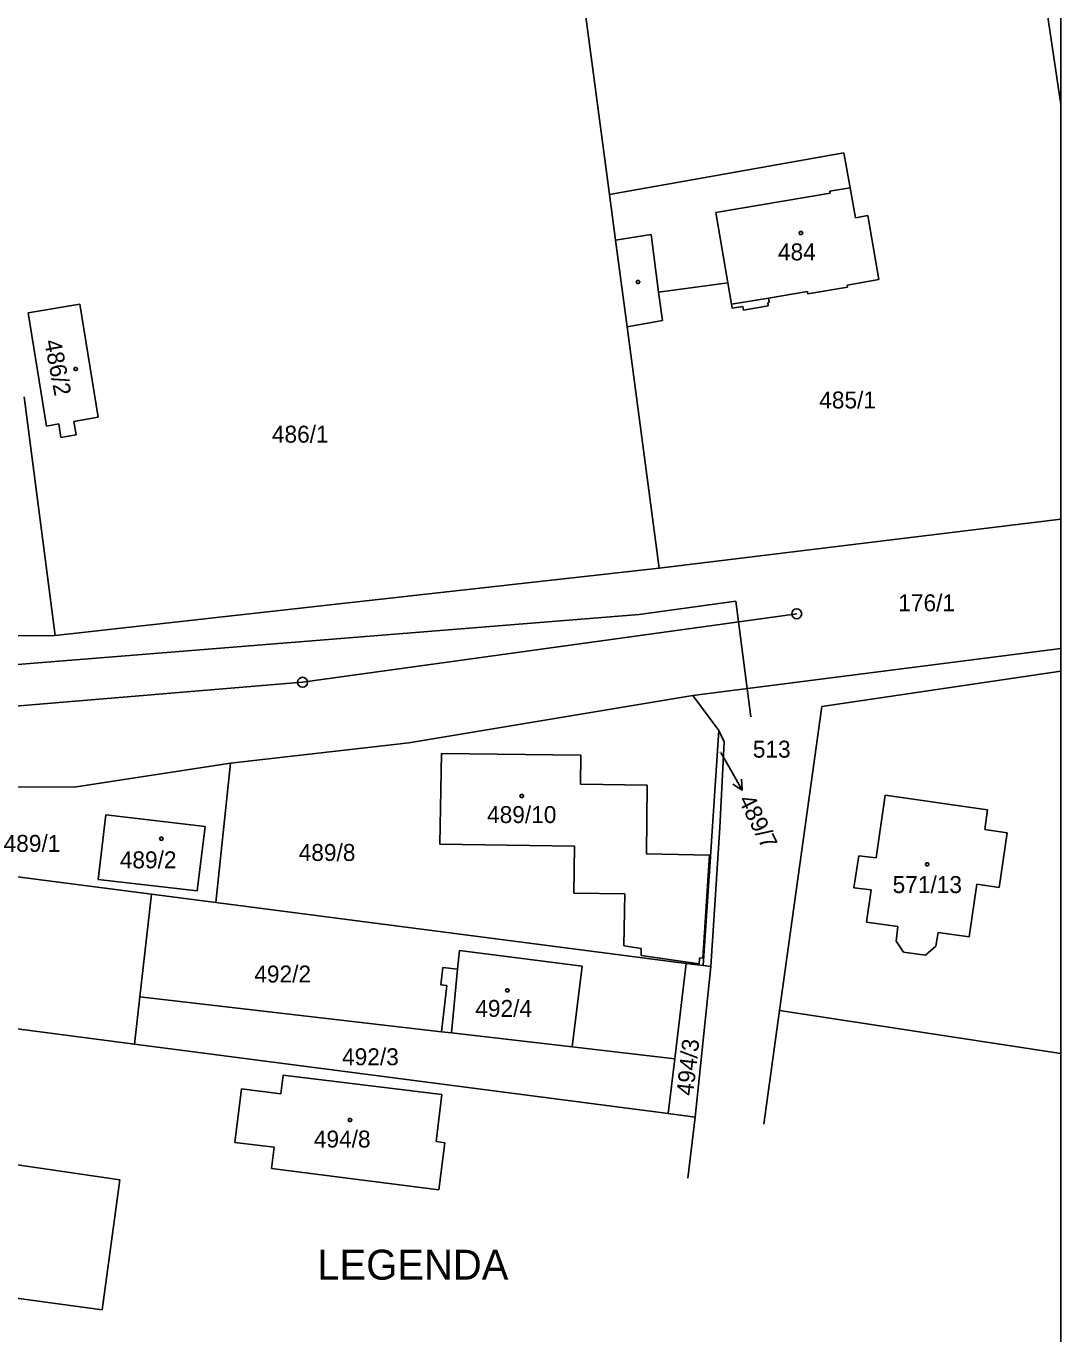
# Model space of a CAD drawing. Extents: x -639621 to -639329, y -1192893 to -1192488.
# Drawn here: x -639433 to -639329.3, y -1192784.8 to -1192653.7 of the extents above; entities that cross this region are included whole.
import ezdxf

# ---------------------------------------------------------------- set-up
doc = ezdxf.new("R2010")
doc.units = 0
for name, color, linetype in [('Vrstva 1', 7, 'Continuous'), ('Vrstva 19', 7, 'Continuous'), ('Vrstva 2', 7, 'Continuous'), ('Vrstva 25', 7, 'Continuous'), ('Vrstva 4', 7, 'Continuous'), ('Vrstva 5', 7, 'Continuous'), ('Vrstva 61', 7, 'Continuous'), ('Vrstva 7', 7, 'Continuous')]:
    doc.layers.add(name, color=color, linetype=linetype)

msp = doc.modelspace()

# ---------------------------------------------------------------- linework, layer by layer
at = {"layer": 'Vrstva 1'}
for p, q in [((-639334.13, -1192628.53), (-639329.26, -1192661.57)), ((-639374.53, -1192670.58), (-639379.36, -1192634.4)), ((-639351.01, -1192666.42), (-639374.53, -1192670.58)), ((-639350.4, -1192669.9), (-639351.01, -1192666.42)), ((-639373.92, -1192675.15), (-639374.53, -1192670.58)), ((-639349.87, -1192672.92), (-639350.4, -1192669.9)), ((-639348.62, -1192672.7), (-639349.87, -1192672.92)), ((-639347.51, -1192679.11), (-639348.62, -1192672.7)), ((-639372.76, -1192683.86), (-639373.92, -1192675.15)), ((-639362.66, -1192679.45), (-639369.6, -1192680.38)), ((-639362.66, -1192679.45), (-639362.3, -1192681.59)), ((-639354.64, -1192680.55), (-639350.65, -1192679.89)), ((-639350.69, -1192679.66), (-639347.51, -1192679.11)), ((-639350.65, -1192679.89), (-639350.69, -1192679.66)), ((-639369.6, -1192680.38), (-639369.22, -1192683.23)), ((-639358.66, -1192681.45), (-639358.51, -1192681.43)), ((-639358.61, -1192681.76), (-639358.66, -1192681.45)), ((-639358.58, -1192680.97), (-639354.68, -1192680.32)), ((-639358.51, -1192681.43), (-639358.58, -1192680.97)), ((-639354.68, -1192680.32), (-639354.64, -1192680.55)), ((-639432.82, -1192682.46), (-639427.64, -1192681.59)), ((-639432.82, -1192682.46), (-639430.98, -1192693.81)), ((-639425.81, -1192692.93), (-639427.64, -1192681.59)), ((-639362.3, -1192681.59), (-639362.23, -1192681.99)), ((-639362.23, -1192681.99), (-639361.16, -1192681.81)), ((-639361.16, -1192681.81), (-639361.1, -1192682.17)), ((-639361.1, -1192682.17), (-639358.61, -1192681.76)), ((-639372.76, -1192683.86), (-639369.22, -1192683.23)), ((-639369.53, -1192708.06), (-639372.76, -1192683.86)), ((-639433.22, -1192690.86), (-639430.11, -1192714.81)), ((-639428.23, -1192693.34), (-639425.81, -1192692.93)), ((-639429.75, -1192693.59), (-639430.98, -1192693.81)), ((-639429.53, -1192694.94), (-639429.75, -1192693.59)), ((-639428.23, -1192693.34), (-639428.01, -1192694.7)), ((-639428.01, -1192694.7), (-639429.53, -1192694.94)), ((-639329.26, -1192703.15), (-639369.53, -1192708.06)), ((-639430.11, -1192714.81), (-639369.53, -1192708.06)), ((-639430.11, -1192714.81), (-639485.5, -1192715.26)), ((-639329.26, -1192716.12), (-639366.16, -1192720.83)), ((-639329.26, -1192718.4), (-639353.22, -1192721.94)), ((-639394.64, -1192725.58), (-639366.16, -1192720.83)), ((-639366.16, -1192720.83), (-639363.55, -1192724.33)), ((-639353.22, -1192721.94), (-639357.47, -1192752.43)), ((-639363.55, -1192724.33), (-639364.42, -1192737.47)), ((-639363.02, -1192725.47), (-639363.55, -1192724.33)), ((-639412.53, -1192727.63), (-639394.64, -1192725.58)), ((-639363.45, -1192734.05), (-639363.02, -1192725.47)), ((-639391.52, -1192735.73), (-639391.38, -1192726.63)), ((-639391.38, -1192726.63), (-639377.39, -1192726.82)), ((-639377.39, -1192726.82), (-639377.44, -1192729.71)), ((-639428.21, -1192730.01), (-639412.53, -1192727.63)), ((-639413.99, -1192741.6), (-639412.53, -1192727.63)), ((-639449.52, -1192729.95), (-639428.21, -1192730.01)), ((-639377.44, -1192729.71), (-639370.74, -1192729.81)), ((-639370.74, -1192729.81), (-639370.8, -1192736.7)), ((-639347.79, -1192737.11), (-639346.87, -1192730.83)), ((-639346.87, -1192730.83), (-639336.62, -1192732.28)), ((-639336.62, -1192732.28), (-639336.9, -1192734.26)), ((-639425.02, -1192732.78), (-639425.8, -1192739.27)), ((-639415.08, -1192733.98), (-639425.02, -1192732.78)), ((-639415.86, -1192740.42), (-639415.08, -1192733.98)), ((-639364.37, -1192748.01), (-639363.45, -1192734.05)), ((-639336.9, -1192734.26), (-639334.64, -1192734.59)), ((-639334.64, -1192734.59), (-639335.46, -1192740.09)), ((-639378.02, -1192735.94), (-639391.52, -1192735.73)), ((-639378.09, -1192740.64), (-639378.02, -1192735.94)), ((-639420.45, -1192740.76), (-639446.92, -1192737.34)), ((-639370.8, -1192736.7), (-639364.51, -1192736.84)), ((-639364.51, -1192736.84), (-639365.17, -1192747.18)), ((-639364.42, -1192737.47), (-639365.12, -1192747.91)), ((-639350.02, -1192740.11), (-639349.53, -1192736.9)), ((-639349.53, -1192736.9), (-639347.79, -1192737.11)), ((-639425.8, -1192739.27), (-639415.86, -1192740.42)), ((-639348.27, -1192740.32), (-639350.02, -1192740.11)), ((-639348.74, -1192743.57), (-639348.27, -1192740.32)), ((-639337.69, -1192739.76), (-639338.44, -1192745.02)), ((-639335.46, -1192740.09), (-639337.69, -1192739.76)), ((-639421.62, -1192751.04), (-639420.45, -1192740.76)), ((-639413.99, -1192741.6), (-639420.45, -1192740.76)), ((-639366.85, -1192747.69), (-639413.99, -1192741.6)), ((-639372.99, -1192740.72), (-639378.09, -1192740.64)), ((-639373.07, -1192745.94), (-639372.99, -1192740.72)), ((-639345.62, -1192744.01), (-639348.74, -1192743.57)), ((-639345.79, -1192745.47), (-639345.62, -1192744.01)), ((-639345.05, -1192746.57), (-639345.79, -1192745.47)), ((-639341.56, -1192744.58), (-639341.79, -1192745.98)), ((-639338.44, -1192745.02), (-639341.56, -1192744.58)), ((-639389.56, -1192746.39), (-639389.75, -1192748.26)), ((-639377.26, -1192747.97), (-639389.56, -1192746.39)), ((-639371.35, -1192746.21), (-639373.07, -1192745.94)), ((-639371.35, -1192746.21), (-639371.36, -1192746.91)), ((-639371.36, -1192746.91), (-639365.54, -1192747.74)), ((-639342.85, -1192746.88), (-639345.05, -1192746.57)), ((-639341.79, -1192745.98), (-639342.85, -1192746.88)), ((-639391.25, -1192748.09), (-639391.45, -1192749.83)), ((-639389.75, -1192748.26), (-639391.25, -1192748.09)), ((-639377.26, -1192747.97), (-639378.25, -1192756.07)), ((-639366.85, -1192747.69), (-639367.98, -1192757.26)), ((-639365.12, -1192747.91), (-639366.85, -1192747.69)), ((-639364.37, -1192748.01), (-639365.94, -1192763.11)), ((-639365.54, -1192747.74), (-639365.5, -1192747.13)), ((-639365.17, -1192747.18), (-639365.5, -1192747.13)), ((-639365.12, -1192747.91), (-639364.37, -1192748.01)), ((-639391.45, -1192749.83), (-639390.85, -1192749.9)), ((-639390.85, -1192749.9), (-639391.38, -1192754.55)), ((-639422.16, -1192755.8), (-639457.18, -1192751.25)), ((-639422.16, -1192755.8), (-639421.62, -1192751.04)), ((-639421.62, -1192751.04), (-639391.38, -1192754.55)), ((-639357.47, -1192752.43), (-639359.06, -1192763.82)), ((-639329.26, -1192756.74), (-639357.47, -1192752.43)), ((-639391.38, -1192754.55), (-639390.38, -1192754.67)), ((-639390.38, -1192754.67), (-639378.25, -1192756.07)), ((-639368.63, -1192762.76), (-639422.16, -1192755.8)), ((-639378.25, -1192756.07), (-639367.98, -1192757.26)), ((-639367.98, -1192757.26), (-639368.63, -1192762.76)), ((-639407.49, -1192760.78), (-639407.26, -1192758.89)), ((-639407.26, -1192758.89), (-639391.33, -1192760.84)), ((-639412.08, -1192765.64), (-639411.41, -1192760.27)), ((-639411.41, -1192760.27), (-639407.49, -1192760.78)), ((-639391.33, -1192760.84), (-639391.92, -1192765.56)), ((-639365.94, -1192763.11), (-639368.63, -1192762.76)), ((-639423.61, -1192769.39), (-639465.28, -1192763.39)), ((-639365.94, -1192763.11), (-639366.68, -1192769.22)), ((-639408.16, -1192766.14), (-639412.08, -1192765.64)), ((-639408.42, -1192768.25), (-639408.16, -1192766.14)), ((-639391.92, -1192765.56), (-639391.03, -1192765.68)), ((-639391.03, -1192765.68), (-639391.65, -1192770.4)), ((-639391.65, -1192770.4), (-639408.42, -1192768.25)), ((-639425.4, -1192782.45), (-639423.61, -1192769.39)), ((-639425.4, -1192782.45), (-639473.03, -1192775.94))]:
    msp.add_line(p, q, dxfattribs=at)
at = {"layer": 'Vrstva 19'}
msp.add_lwpolyline([(-639355.75, -1192712.63), (-639405.3, -1192719.5), (-639444.91, -1192722.8), (-639491, -1192720.22), (-639511.44, -1192713.33)], dxfattribs=at)
for centre in [(-639355.75, -1192712.63), (-639405.3, -1192719.5)]:
    msp.add_circle(centre, 0.5, dxfattribs=at)
at = {"layer": 'Vrstva 25'}
for p, q in [((-639371.54, -1192712.72), (-639361.85, -1192711.36)), ((-639361.85, -1192711.36), (-639360.35, -1192722.96)), ((-639454.38, -1192719.35), (-639371.54, -1192712.72))]:
    msp.add_line(p, q, dxfattribs=at)
at = {"layer": 'Vrstva 4'}
for p, q in [((-639352.4, -1192670.45), (-639363.85, -1192672.38)), ((-639350.4, -1192669.9), (-639352.43, -1192670.24)), ((-639352.43, -1192670.24), (-639352.4, -1192670.45)), ((-639363.85, -1192672.38), (-639362.66, -1192679.45)), ((-639373.92, -1192675.15), (-639370.36, -1192674.6)), ((-639370.36, -1192674.6), (-639369.6, -1192680.38)), ((-639358.58, -1192680.97), (-639362.3, -1192681.59)), ((-639389.75, -1192748.26), (-639390.38, -1192754.67))]:
    msp.add_line(p, q, dxfattribs=at)
at = {"layer": 'Vrstva 5'}
for points in [[(-639355.24, -1192674.3), (-639355.15, -1192674.45), (-639355.24, -1192674.6), (-639355.42, -1192674.6), (-639355.51, -1192674.45), (-639355.42, -1192674.3)], [(-639371.57, -1192679.2), (-639371.48, -1192679.35), (-639371.57, -1192679.5), (-639371.75, -1192679.5), (-639371.84, -1192679.35), (-639371.75, -1192679.2)], [(-639427.96, -1192687.93), (-639427.87, -1192688.08), (-639427.96, -1192688.23), (-639428.14, -1192688.23), (-639428.23, -1192688.08), (-639428.14, -1192687.93)], [(-639383.23, -1192730.77), (-639383.14, -1192730.92), (-639383.23, -1192731.07), (-639383.41, -1192731.07), (-639383.5, -1192730.92), (-639383.41, -1192730.77)], [(-639419.38, -1192735.04), (-639419.29, -1192735.19), (-639419.38, -1192735.34), (-639419.56, -1192735.34), (-639419.65, -1192735.19), (-639419.56, -1192735.04)], [(-639342.58, -1192737.6), (-639342.49, -1192737.75), (-639342.58, -1192737.9), (-639342.76, -1192737.9), (-639342.85, -1192737.75), (-639342.76, -1192737.6)], [(-639384.67, -1192750.25), (-639384.58, -1192750.4), (-639384.67, -1192750.55), (-639384.85, -1192750.55), (-639384.94, -1192750.4), (-639384.85, -1192750.25)], [(-639400.45, -1192763.25), (-639400.36, -1192763.4), (-639400.45, -1192763.55), (-639400.63, -1192763.55), (-639400.72, -1192763.4), (-639400.63, -1192763.25)]]:
    msp.add_lwpolyline(points, close=True, dxfattribs=at)
at = {"layer": 'Vrstva 61'}
msp.add_lwpolyline([(-639329.26, -1192487.83), (-639329.26, -1192893.33)], dxfattribs=at)
at = {"layer": 'Vrstva 7'}
for p in [(-639363.36, -1192726.57), (-639361.22, -1192730.33)]:
    msp.add_line(p, (-639362.7, -1192727.72), dxfattribs=at)
msp.add_lwpolyline([(-639361.28, -1192729.21), (-639361.22, -1192730.33), (-639362.15, -1192729.71)], dxfattribs=at)

# ---------------------------------------------------------------- texts
at = {"layer": 'Vrstva 2'}
for s, height, p in [('484', 1.7, (-639357.63, -1192677.19)), ('485/1', 1.7, (-639353.49, -1192692.04)), ('486/1', 1.7, (-639408.38, -1192695.47)), ('176/1', 1.7, (-639345.56, -1192712.38)), ('513', 1.7, (-639360.15, -1192727.06)), ('489/7', 0.1, (-639363.56, -1192726.57)), ('489/10', 1.7, (-639386.8, -1192733.62)), ('489/1', 1.7, (-639435.28, -1192736.51)), ('489/2', 1.7, (-639423.63, -1192738.16)), ('489/8', 1.7, (-639405.69, -1192737.42)), ('571/13', 1.7, (-639346.13, -1192740.64)), ('492/2', 1.7, (-639410.14, -1192749.61)), ('492/4', 1.7, (-639387.98, -1192753.06)), ('492/3', 1.7, (-639401.34, -1192757.91)), ('494/8', 1.7, (-639404.17, -1192766.16))]:
    msp.add_text(s, height=height, dxfattribs=at).set_placement(p)
for s, rotation, p in [('486/2', 280.8639, (-639431.22, -1192685.29)), ('494/3', 83.5945, (-639366.14, -1192761.02))]:
    msp.add_text(s, height=1.7, rotation=rotation, dxfattribs=at).set_placement(p)
at = {"layer": 'Vrstva 61'}
msp.add_text('LEGENDA', height=3, dxfattribs=at).set_placement((-639403.83, -1192779.41))
at = {"layer": 'Vrstva 7'}
msp.add_text('489/7', height=1.7, rotation=296.3338, dxfattribs=at).set_placement((-639361.64, -1192731.3))

doc.saveas('drawing.dxf')
